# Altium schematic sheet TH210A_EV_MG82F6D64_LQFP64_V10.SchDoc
size 337 x 228 mm
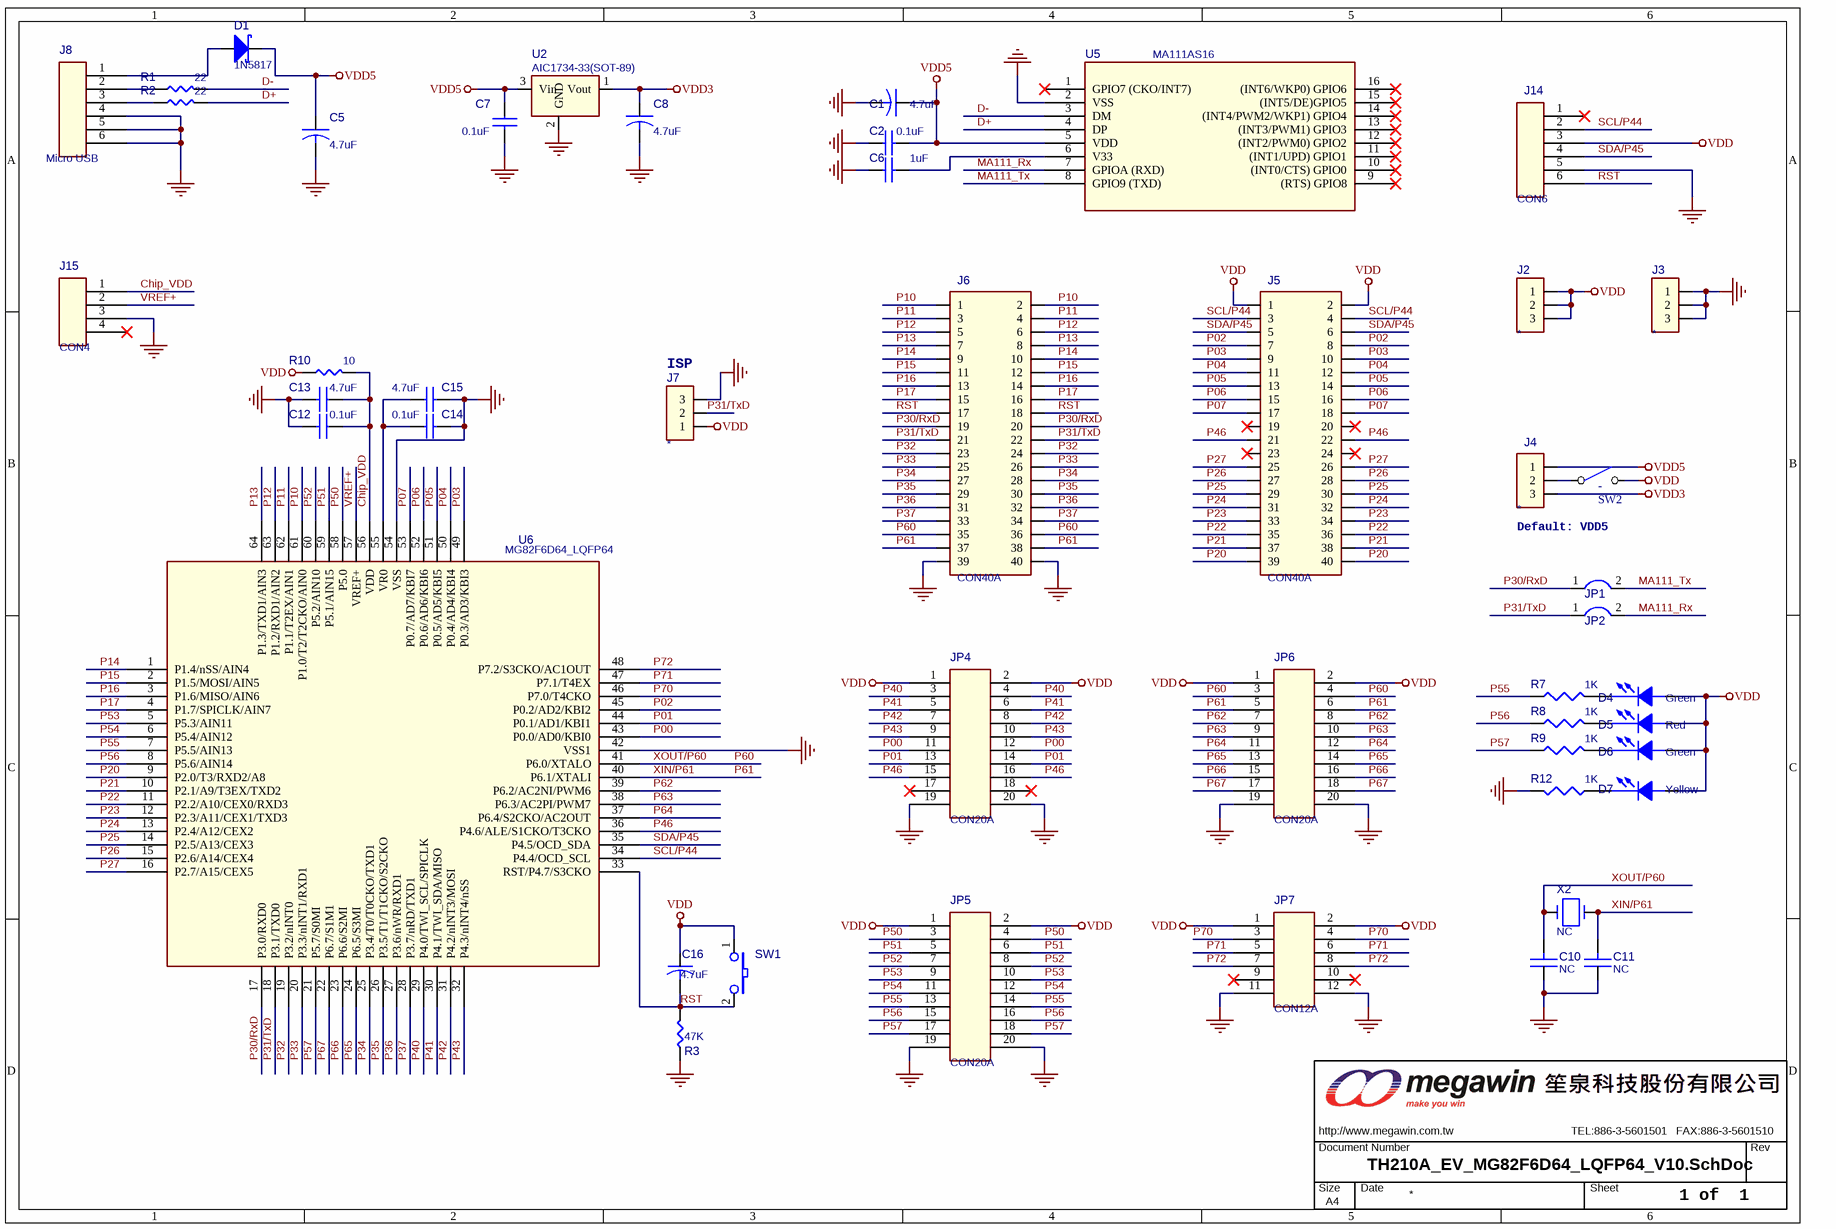
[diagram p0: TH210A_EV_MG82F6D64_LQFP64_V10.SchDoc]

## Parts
C1  4.7uF  [0805C]
C2  0.1uF  [0805C]
C5  4.7uF  [0805C]
C6  1uF  [0805C]
C7  0.1uF  [0805C]
C8  4.7uF  [0805C]
C10  NC  [0805C]
C11  NC  [0805C]
C12  0.1uF  [0805C]
C13  4.7uF  [0805C]
C14  0.1uF  [0805C]
C15  4.7uF  [0805C]
C16  4.7uF  [0805C]
D1  1N5817  [D5817_SMD_1]
D4  Green  [0805D]
D5  Red  [0805D]
D6  Green  [0805D]
D7  Yellow  [0805D]
J2  *  [PS3P254]
J3  *  [PS3P254]
J4  *  [JUMP3_SMD]
J5  CON40A  [PS20X2P254]
J6  CON40A  [PS20X2P254]
J7  *  [PS3P254f_90]
J8  Micro USB  [JACK_USB_SMD290X220P065]
J14  CON6  [PS6P254F_90]
J15  CON4  [PS4P254]
JP1  JUMPER2  [PS2P254]  (value not drawn)
JP2  JUMPER2  [PS2P254]  (value not drawn)
JP4  CON20A  [PS10X2P254]
JP5  CON20A  [PS10X2P254]
JP6  CON20A  [PS10X2P254]
JP7  CON12A  [PS6X2P254]
MW1  OrgAddr3: TEL:886-3-5601501   FAX:886-3-5601510  Page Size: A4  [MEGAWIN_T]  (hidden comment: MW-A4)  (no BOM)
R1  22  [0805R]
R2  22  [0805R]
R3  47K  [0805R]
R7  1K  [0805R]
R8  1K  [0805R]
R9  1K  [0805R]
R10  10  [0805R]
R12  1K  [0805R]
SW1  SW TACT-SPST  [SW_T_2P]  (value not drawn)
SW2  -  [DIP2_SW]
U2  AIC1734-33(SOT-89)  [SOT89]
U5  MA111AS16  [SO16_150P127]
U6  MG82F6D64_LQFP64  [QFP64_7X7P040]
X2  NC  [X49U]

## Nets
GND_POWER: C1.2 C2.1 C5.2 C6.1 C7.2 C8.2 C10.1 C11.1 C12.2 C13.2 C14.2 C15.2 J3.1 J3.2 J3.3 J6.39 J6.40 J7.3 J8.4 J8.5 J8.6 J14.5 J15.3 JP4.19 JP4.20 JP5.19 JP5.20 JP6.19 JP6.20 JP7.11 JP7.12 R3.1 R12.1 U2.2(GND) U5.2(VSS) U6.42(VSS1) U6.54(VSS)
VDD: C16.1(POS) D4.1(ANODE) D5.1(ANODE) D6.1(ANODE) D7.1(ANODE) J2.1 J2.2 J2.3 J5.1 J5.2 J7.1 J14.3 JP4.1 JP4.2 JP5.1 JP5.2 JP6.1 JP6.2 JP7.1 JP7.2 R10.1 SW1.1 SW2.2(NO)
VDD3: C8.1 J4.3 U2.1(Vout)
VDD5: C1.1 C2.2 C5.1 C7.1 D1.2(K) J4.1 U2.3(Vin) U5.5(VDD)
Chip_VDD: C12.1 C13.1 J15.1 R10.2 U6.56(VDD)
D+: R2.2 U5.4(DP)
D-: R1.2 U5.3(DM)
MA111_Rx: JP2.2 U5.7(GPIOA_(RXD))
MA111_Tx: JP1.2 U5.8(GPIO9_(TXD))
P00: JP4.11 JP4.12 U6.43(P0.0/AD0/KBI0)
P01: JP4.13 JP4.14 U6.44(P0.1/AD1/KBI1)
P02: J5.7 J5.8 U6.45(P0.2/AD2/KBI2)
P03: J5.9 J5.10 U6.49(P0.3/AD3/KBI3)
P04: J5.11 J5.12 U6.50(P0.4/AD4/KBI4)
P05: J5.13 J5.14 U6.51(P0.5/AD5/KBI5)
P06: J5.15 J5.16 U6.52(P0.6/AD6/KBI6)
P07: J5.17 J5.18 U6.53(P0.7/AD7/KBI7)
P10: J6.1 J6.2 U6.61(P1.0/T2/T2CKO/AIN0)
P11: J6.3 J6.4 U6.62(P1.1/T2EX/AIN1)
P12: J6.5 J6.6 U6.63(P1.2/RXD1/AIN2)
P13: J6.7 J6.8 U6.64(P1.3/TXD1/AIN3)
P14: J6.9 J6.10 U6.1(P1.4/nSS/AIN4)
P15: J6.11 J6.12 U6.2(P1.5/MOSI/AIN5)
P16: J6.13 J6.14 U6.3(P1.6/MISO/AIN6)
P17: J6.15 J6.16 U6.4(P1.7/SPICLK/AIN7)
P20: J5.39 J5.40 U6.9(P2.0/T3/RXD2/A8)
P21: J5.37 J5.38 U6.10(P2.1/A9/T3EX/TXD2)
P22: J5.35 J5.36 U6.11(P2.2/A10/CEX0/RXD3)
P23: J5.33 J5.34 U6.12(P2.3/A11/CEX1/TXD3)
P24: J5.31 J5.32 U6.13(P2.4/A12/CEX2)
P25: J5.29 J5.30 U6.14(P2.5/A13/CEX3)
P26: J5.27 J5.28 U6.15(P2.6/A14/CEX4)
P27: J5.25 J5.26 U6.16(P2.7/A15/CEX5)
P30/RxD: J6.19 J6.20 JP1.1 U6.17(P3.0/RXD0)
P31/TxD: J6.21 J6.22 J7.2 JP2.1 U6.18(P3.1/TXD0)
P32: J6.23 J6.24 U6.19(P3.2/nINT0)
P33: J6.25 J6.26 U6.20(P3.3/nINT1/RXD1)
P34: J6.27 J6.28 U6.25(P3.4/T0/T0CKO/TXD1)
P35: J6.29 J6.30 U6.26(P3.5/T1/T1CKO/S2CKO)
P36: J6.31 J6.32 U6.27(P3.6/nWR/RXD1)
P37: J6.33 J6.34 U6.28(P3.7/nRD/TXD1)
P40: JP4.3 JP4.4 U6.29(P4.0/TWI_SCL/SPICLK)
P41: JP4.5 JP4.6 U6.30(P4.1/TWI_SDA/MISO)
P42: JP4.7 JP4.8 U6.31(P4.2/nINT3/MOSI)
P43: JP4.9 JP4.10 U6.32(P4.3/nINT4/nSS)
P46: J5.21 J5.22 JP4.15 JP4.16 U6.36(P4.6/ALE/S1CKO/T3CKO)
P50: JP5.3 JP5.4 U6.58(P5.0)
P51: JP5.5 JP5.6 U6.59(P5.1/AIN15)
P52: JP5.7 JP5.8 U6.60(P5.2/AIN10)
P53: JP5.9 JP5.10 U6.5(P5.3/AIN11)
P54: JP5.11 JP5.12 U6.6(P5.4/AIN12)
P55: JP5.13 JP5.14 R7.1 U6.7(P5.5/AIN13)
P56: JP5.15 JP5.16 R8.1 U6.8(P5.6/AIN14)
P57: JP5.17 JP5.18 R9.1 U6.21(P5.7/S0MI)
P60: C10.2 J6.35 J6.36 JP6.3 JP6.4 U6.41(P6.0/XTALO) X2.2  [also labelled XOUT/P60]
P61: C11.2 J6.37 J6.38 JP6.5 JP6.6 U6.40(P6.1/XTALI) X2.1  [also labelled XIN/P61]
P62: JP6.7 JP6.8 U6.39(P6.2/AC2NI/PWM6)
P63: JP6.9 JP6.10 U6.38(P6.3/AC2PI/PWM7)
P64: JP6.11 JP6.12 U6.37(P6.4/S2CKO/AC2OUT)
P65: JP6.13 JP6.14 U6.24(P6.5/S3MI)
P66: JP6.15 JP6.16 U6.23(P6.6/S2MI)
P67: JP6.17 JP6.18 U6.22(P6.7/S1M1)
P70: JP7.3 JP7.4 U6.46(P7.0/T4CKO)
P71: JP7.5 JP7.6 U6.47(P7.1/T4EX)
P72: JP7.7 JP7.8 U6.48(P7.2/S3CKO/AC1OUT)
RST: C16.2(NEG) J6.17 J6.18 J14.6 R3.2 SW1.2 U6.33(RST/P4.7/S3CKO)
SCL/P44: J5.3 J5.4 J14.2 U6.34(P4.4/OCD_SCL)
SDA/P45: J5.5 J5.6 J14.4 U6.35(P4.5/OCD_SDA)
VREF+: J15.2 U6.57(VREF+)
NetC6_2: C6.2 U5.6(V33)
NetC14_1: C14.1 C15.1 U6.55(VR0)
NetD1_1: D1.1(A) J8.1
NetD4_2: D4.2(CATHODE) R7.2
NetD5_2: D5.2(CATHODE) R8.2
NetD6_2: D6.2(CATHODE) R9.2
NetD7_2: D7.2(CATHODE) R12.2
NetJ4_2: J4.2 SW2.1(COMMON)
NetJ8_2: J8.2 R1.1
NetJ8_3: J8.3 R2.1

Not connected (* = marked no-connect by the designer): J5 19* 20* 23* 24*; J14 1*; J15 4*; JP4 17* 18*; JP7 9* 10*; U5 1(GPIO7_(CKO/INT7))* 9((RTS)_GPIO8)* 10((INT0/CTS)_GPIO0)* 11((INT1/UPD)_GPIO1)* 12((INT2/PWM0)_GPIO2)* 13((INT3/PWM1)_GPIO3)* 14((INT4/PWM2/WKP1)_GPIO4)* 15((INT5/DE)GPIO5)* 16((INT6/WKP0)_GPIO6)*

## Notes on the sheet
- (near J7) ISP
- Default: VDD5
- 1 of  1

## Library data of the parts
C1 C5 C8 = CAP
C2 C6 C7 C12-C15 = CAP NP
C10 C11 = C NP
C16 = C
D1 = DIODE_ZD: Schottky Diode
D4-D7 = LED
J2-J4 J7 = CON3
J8 = CON6
JP7 = CON12A_0
MW1 = MW_A4_1
R1-R3 R10 = R
R7-R9 R12 = R_Dup2
SW2 = SW-2
U2 = AIC1734-33(SOT-89)_0
U6 = FA245_LQFP64_0
X2 = CRYSTAL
